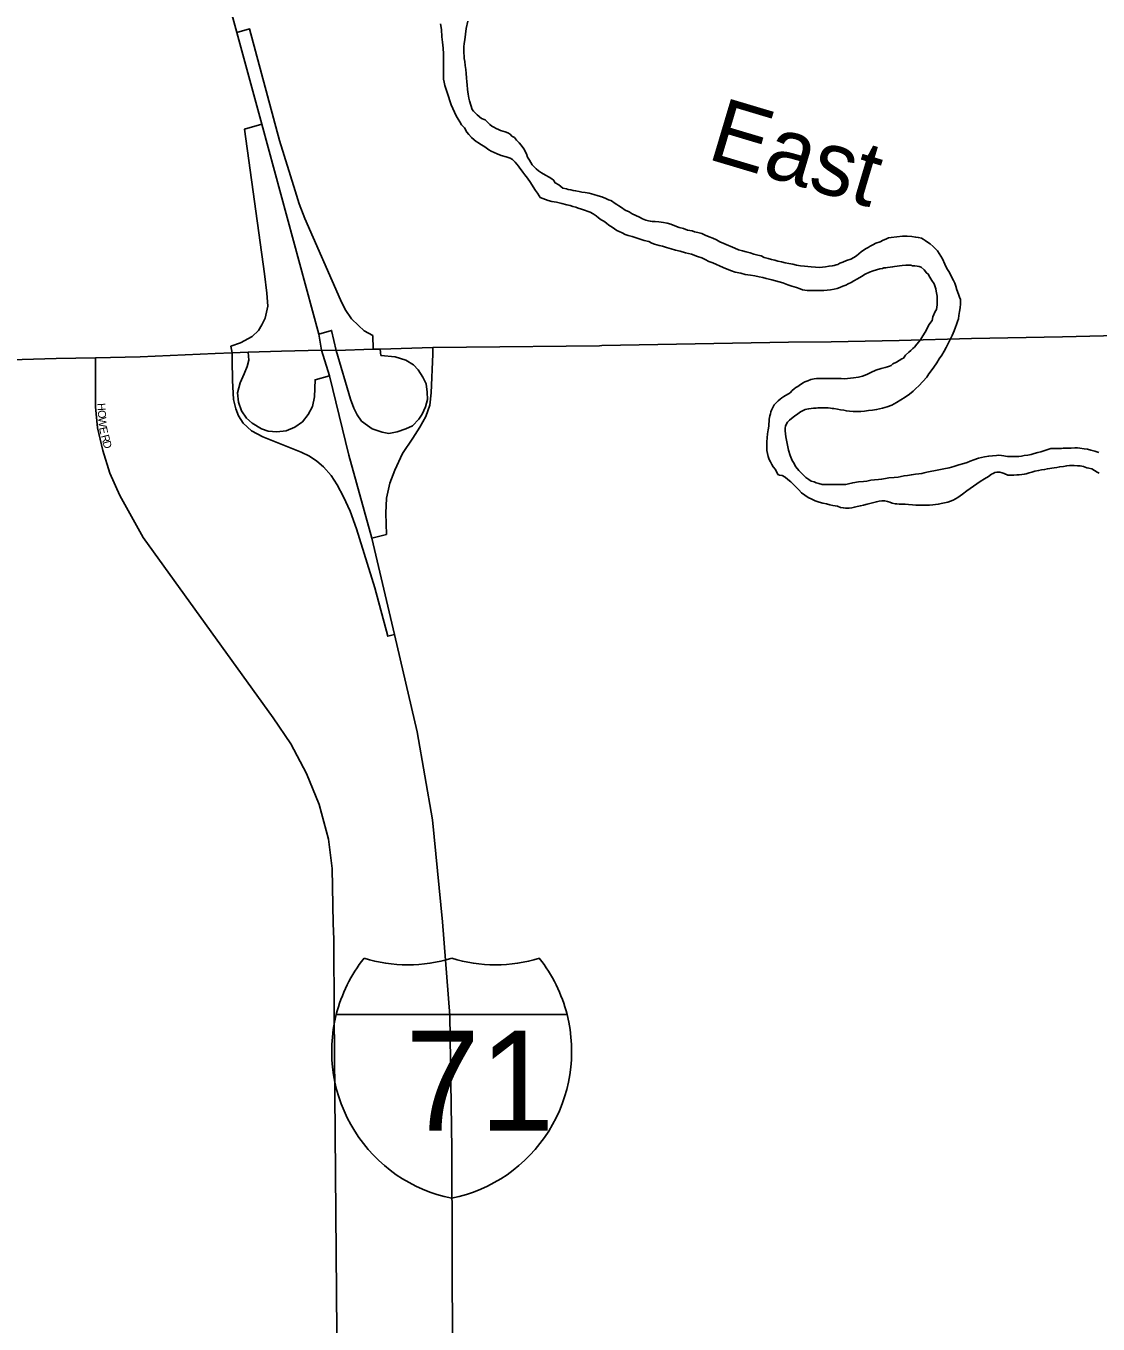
# Model space of a CAD drawing. Extents: x -561 to 1170, y 0 to 846.
# Drawn here: x 151.52 to 169.61, y 88.46 to 110.36 of the extents above; entities that cross this region are included whole.
import ezdxf

# ---------------------------------------------------------------- set-up
doc = ezdxf.new("R2010")
doc.units = 0
for name, color, linetype in [('GM_X_City_Street', 7, 'Continuous'), ('GM_X_City_Street_Text', 7, 'Continuous'), ('GM_X_Interchange_Ramps', 7, 'Continuous'), ('GM_X_Interstate_Location', 7, 'Continuous'), ('GM_X_Interstate_Route', 7, 'Continuous'), ('GM_X_Interstate_Shield', 7, 'Continuous'), ('GM_X_Major_River', 7, 'Continuous'), ('GM_X_Major_River_Text', 7, 'Continuous'), ('GM_X_State_Route', 7, 'Continuous')]:
    doc.layers.add(name, color=color, linetype=linetype)

msp = doc.modelspace()

# ---------------------------------------------------------------- linework, layer by layer
at = {"layer": 'GM_X_City_Street'}
for points in [[(156.71, 95.219), (156.688, 96.145), (156.628, 96.639), (156.469, 97.228), (156.258, 97.751), (155.993, 98.252), (155.695, 98.69), (153.504, 101.729), (153.108, 102.442), (152.94, 102.819), (152.819, 103.197), (152.731, 103.581), (152.697, 103.938), (152.697, 104.764)], [(156.783, 86.988), (156.727, 93.684), (156.717, 94.954), (156.71, 95.219)]]:
    msp.add_lwpolyline(points, dxfattribs=at)
at = {"layer": 'GM_X_Interchange_Ramps'}
for points in [[(157.384, 104.908), (157.378, 105.138), (157.232, 105.219), (157.134, 105.306), (157.015, 105.423), (156.912, 105.579), (156.833, 105.741), (156.232, 107.111), (156.134, 107.36), (156.067, 107.578), (155.803, 108.427), (155.296, 110.312), (155.084, 110.252)], [(155.505, 108.702), (155.21, 108.619), (155.55, 106.182), (155.59, 105.851), (155.604, 105.635), (155.563, 105.432), (155.502, 105.317), (155.445, 105.221), (155.34, 105.121), (155.144, 105.013), (154.982, 104.959), (155.002, 104.847)], [(157.503, 104.911), (157.513, 104.804), (157.754, 104.777), (157.934, 104.725), (158.061, 104.645), (158.14, 104.562), (158.223, 104.435), (158.275, 104.322), (158.295, 104.183), (158.297, 104.061), (158.265, 103.935), (158.207, 103.81), (158.151, 103.726), (158.047, 103.614), (157.932, 103.563), (157.79, 103.513), (157.645, 103.486), (157.533, 103.506), (157.367, 103.563), (157.286, 103.618), (157.188, 103.695), (157.114, 103.803), (157.057, 103.915), (156.999, 104.064), (156.756, 104.888), (156.681, 105.224), (156.466, 105.162)], [(157.361, 101.719), (157.605, 101.782), (157.598, 102.14), (157.608, 102.392), (157.662, 102.648), (157.747, 102.867), (157.878, 103.148), (158.052, 103.409), (158.17, 103.59), (158.27, 103.77), (158.341, 103.964), (158.364, 104.171), (158.392, 104.826), (158.387, 104.939)], [(155.002, 104.847), (155.002, 104.723), (155.01, 104.379), (155.027, 104.058), (155.065, 103.904), (155.11, 103.784), (155.187, 103.66), (155.329, 103.532), (155.521, 103.43), (156.17, 103.169), (156.309, 103.106), (156.433, 103.017), (156.542, 102.923), (156.672, 102.779), (156.773, 102.618), (156.884, 102.416), (156.993, 102.174), (157.1, 101.875), (157.411, 100.882), (157.63, 100.066), (157.741, 100.094)], [(156.647, 104.458), (156.402, 104.393), (156.392, 104.102), (156.361, 103.94), (156.288, 103.805), (156.193, 103.683), (156.062, 103.594), (155.915, 103.533), (155.757, 103.515), (155.61, 103.524), (155.501, 103.565), (155.342, 103.661), (155.246, 103.747), (155.161, 103.87), (155.11, 104.015), (155.096, 104.173), (155.136, 104.338), (155.207, 104.494), (155.256, 104.617), (155.287, 104.721), (155.275, 104.86)]]:
    msp.add_lwpolyline(points, dxfattribs=at)
at = {"layer": 'GM_X_Interstate_Route'}
for points in [[(156.513, 104.891), (156.466, 105.162), (155.505, 108.702), (155.084, 110.252), (153.768, 115.093), (153.127, 117.482), (152.86, 118.791), (152.62, 120.081), (152.498, 121.009), (152.35, 122.472), (152.22, 124.261)], [(159.707, 72.107), (159.003, 79.45), (158.736, 82.784), (158.71, 91.411), (158.678, 93.667), (158.555, 95.249), (158.385, 96.969), (158.124, 98.452), (157.741, 100.094), (157.361, 101.719), (156.974, 103.122), (156.647, 104.458), (156.513, 104.891)]]:
    msp.add_lwpolyline(points, dxfattribs=at)
at = {"layer": 'GM_X_Interstate_Shield'}
for p, q in [((156.76, 93.682), (160.655, 93.682)), ((160.655, 93.682), (156.76, 93.682)), ((160.655, 93.682), (156.76, 93.682))]:
    msp.add_line(p, q, dxfattribs=at)
for centre, start, end in [((159.214, 93.062), 141.669, 165.8066), ((157.968, 97.052), 253.0091, 286.9909), ((159.447, 97.052), 253.0091, 286.9909), ((158.201, 93.062), 14.1934, 38.331), ((159.214, 93.062), 165.8066, 258.463), ((158.201, 93.062), 281.537, 14.1934)]:
    msp.add_arc(centre, 2.531, start, end, dxfattribs=at)
at = {"layer": 'GM_X_Major_River'}
for points in [[(162.563, 106.562), (162.482, 106.577), (162.411, 106.603), (162.335, 106.624), (162.264, 106.645), (162.21, 106.655), (162.172, 106.671), (162.129, 106.681), (162.085, 106.697), (162.036, 106.723), (161.955, 106.744), (161.889, 106.765), (161.819, 106.786), (161.754, 106.807), (161.688, 106.827), (161.634, 106.843), (161.585, 106.87), (161.531, 106.891), (161.493, 106.912), (161.454, 106.938), (161.416, 106.965), (161.362, 107.002), (161.318, 107.034), (161.274, 107.066), (161.231, 107.093), (161.187, 107.125), (161.143, 107.157), (161.094, 107.189), (161.045, 107.22), (160.996, 107.236), (160.964, 107.247), (160.931, 107.257), (160.898, 107.273), (160.844, 107.288), (160.8, 107.304), (160.752, 107.314), (160.708, 107.33), (160.648, 107.346), (160.567, 107.366), (160.475, 107.387), (160.399, 107.402), (160.334, 107.418), (160.29, 107.433), (160.203, 107.47), (160.181, 107.497), (160.154, 107.54), (160.121, 107.588), (160.082, 107.647), (160.038, 107.723), (159.988, 107.793), (159.944, 107.852), (159.906, 107.894), (159.878, 107.932), (159.856, 107.964), (159.834, 107.996), (159.806, 108.029), (159.779, 108.066), (159.735, 108.109), (159.692, 108.13), (159.626, 108.151), (159.545, 108.177), (159.474, 108.203), (159.425, 108.224), (159.371, 108.251), (159.333, 108.272), (159.289, 108.304), (159.251, 108.331), (159.202, 108.362), (159.158, 108.389), (159.12, 108.41), (159.087, 108.442), (159.043, 108.48), (158.999, 108.528), (158.961, 108.571), (158.922, 108.641), (158.873, 108.694), (158.845, 108.743), (158.817, 108.791), (158.784, 108.845), (158.756, 108.909), (158.728, 108.969), (158.701, 109.028), (158.678, 109.098), (158.655, 109.174), (158.633, 109.238), (158.616, 109.292), (158.594, 109.357), (158.582, 109.411), (158.571, 109.465), (158.57, 109.53), (158.569, 109.606), (158.57, 109.893), (158.564, 109.985), (158.552, 110.088), (158.54, 110.18), (158.533, 110.299), (158.52, 110.396)], [(158.98, 110.44), (158.954, 110.32), (158.939, 110.223), (158.93, 110.13), (158.92, 110.065), (158.915, 110.011), (158.91, 109.978), (158.91, 109.941), (158.911, 109.897), (158.917, 109.865), (158.918, 109.811), (158.929, 109.762), (158.935, 109.697), (158.947, 109.627), (158.953, 109.562), (158.96, 109.486), (158.961, 109.421), (158.967, 109.367), (158.973, 109.291), (158.985, 109.21), (158.997, 109.145), (159.008, 109.097), (159.053, 108.951), (159.075, 108.924), (159.136, 108.86), (159.212, 108.801), (159.272, 108.775), (159.321, 108.727), (159.354, 108.7), (159.387, 108.673), (159.42, 108.652), (159.458, 108.631), (159.496, 108.615), (159.534, 108.599), (159.572, 108.589), (159.61, 108.573), (159.654, 108.558), (159.692, 108.536), (159.725, 108.504), (159.768, 108.478), (159.801, 108.435), (159.845, 108.392), (159.878, 108.349), (159.906, 108.311), (159.928, 108.285), (159.944, 108.252), (159.972, 108.204), (159.989, 108.15), (160.022, 108.096), (160.044, 108.059), (160.066, 108.021), (160.094, 107.989), (160.132, 107.951), (160.17, 107.919), (160.225, 107.882), (160.29, 107.845), (160.35, 107.808), (160.399, 107.781), (160.427, 107.76), (160.454, 107.712), (160.514, 107.68), (160.547, 107.653), (160.585, 107.626), (160.645, 107.611), (160.672, 107.6), (160.716, 107.596), (160.759, 107.585), (160.797, 107.58), (160.857, 107.57), (160.905, 107.56), (160.96, 107.55), (161.025, 107.54), (161.106, 107.519), (161.182, 107.498), (161.242, 107.477), (161.307, 107.451), (161.356, 107.43), (161.394, 107.414), (161.421, 107.398), (161.449, 107.377), (161.492, 107.35), (161.53, 107.329), (161.574, 107.297), (161.634, 107.255)], [(161.634, 107.255), (161.7, 107.223), (161.754, 107.191), (161.814, 107.165), (161.874, 107.133), (161.928, 107.107), (161.983, 107.086), (162.026, 107.075), (162.059, 107.07), (162.091, 107.06), (162.14, 107.061), (162.205, 107.056), (162.281, 107.046), (162.346, 107.036), (162.405, 107.015), (162.471, 106.989), (162.547, 106.963), (162.617, 106.942), (162.688, 106.916), (162.764, 106.906), (162.807, 106.89), (162.862, 106.874), (162.927, 106.859), (162.987, 106.833), (163.052, 106.806), (163.117, 106.78), (163.177, 106.754), (163.232, 106.722), (163.297, 106.69), (163.487, 106.611), (163.547, 106.585), (163.612, 106.569), (163.677, 106.549), (163.742, 106.533), (163.808, 106.512), (163.873, 106.497), (163.927, 106.481), (163.981, 106.455), (164.047, 106.439), (164.106, 106.424), (164.161, 106.408), (164.21, 106.393), (164.275, 106.382), (164.334, 106.367), (164.399, 106.352), (164.464, 106.341), (164.524, 106.326), (164.595, 106.316), (164.66, 106.311), (164.719, 106.301), (164.773, 106.297), (164.849, 106.292), (164.909, 106.287), (164.963, 106.293), (165.017, 106.299), (165.076, 106.311), (165.13, 106.312), (165.163, 106.318), (165.195, 106.329), (165.222, 106.335), (165.259, 106.357), (165.308, 106.379), (165.372, 106.407), (165.442, 106.429), (165.496, 106.457), (165.539, 106.485), (165.576, 106.518), (165.619, 106.551), (165.657, 106.578), (165.7, 106.606), (165.737, 106.622), (165.77, 106.645), (165.812, 106.667), (165.866, 106.694), (165.936, 106.722), (165.99, 106.745), (166.033, 106.767), (166.076, 106.784), (166.125, 106.795), (166.314, 106.814), (166.395, 106.815), (166.471, 106.81), (166.536, 106.8), (166.584, 106.79), (166.633, 106.78), (166.666, 106.764), (166.699, 106.743), (166.737, 106.716), (166.781, 106.684), (166.83, 106.641), (166.874, 106.604), (166.907, 106.566), (166.934, 106.523), (166.962, 106.48), (166.989, 106.432), (167.028, 106.34), (167.062, 106.27), (167.095, 106.217), (167.123, 106.168), (167.145, 106.12), (167.173, 106.066)], [(166.126, 104.634), (166.153, 104.661), (166.212, 104.689), (166.26, 104.717), (166.303, 104.744), (166.33, 104.756), (166.367, 104.805), (166.42, 104.86), (166.458, 104.887), (166.49, 104.92), (166.517, 104.942), (166.559, 104.991), (166.591, 105.03), (166.618, 105.068), (166.639, 105.106), (166.713, 105.226), (166.734, 105.275), (166.766, 105.324), (166.792, 105.362), (166.814, 105.39), (166.829, 105.455), (166.866, 105.542), (166.887, 105.575), (166.892, 105.618), (166.902, 105.656), (166.9, 105.803), (166.883, 105.889), (166.877, 105.927), (166.849, 106.013), (166.81, 106.067), (166.777, 106.121), (166.749, 106.174), (166.717, 106.196), (166.683, 106.249), (166.629, 106.292), (166.596, 106.303), (166.564, 106.308), (166.52, 106.313), (166.482, 106.317), (166.455, 106.323), (166.417, 106.327), (166.369, 106.327), (166.309, 106.321), (166.18, 106.303), (166.147, 106.297), (166.104, 106.291), (166.061, 106.285), (166.029, 106.279), (166.001, 106.279), (165.975, 106.268), (165.931, 106.262), (165.878, 106.245), (165.818, 106.228), (165.759, 106.206), (165.684, 106.172), (165.625, 106.134), (165.555, 106.095), (165.496, 106.062), (165.448, 106.034), (165.399, 106.012), (165.356, 105.989), (165.308, 105.973), (165.259, 105.95), (165.211, 105.934), (165.162, 105.922), (165.098, 105.911), (164.99, 105.898), (164.908, 105.897), (164.827, 105.896), (164.762, 105.896), (164.708, 105.9), (164.665, 105.905), (164.627, 105.91), (164.589, 105.926), (164.524, 105.947), (164.448, 105.973), (164.377, 105.994), (164.295, 106.025), (164.236, 106.046), (164.171, 106.062), (164.111, 106.077), (164.062, 106.087), (164.013, 106.103), (163.959, 106.119), (163.894, 106.129), (163.823, 106.144), (163.747, 106.159), (163.661, 106.169), (163.585, 106.19), (163.492, 106.21), (163.427, 106.231), (163.357, 106.258), (163.291, 106.284), (163.112, 106.363), (163.047, 106.389), (162.987, 106.421), (162.927, 106.447), (162.856, 106.473), (162.753, 106.51), (162.655, 106.536), (162.563, 106.562)], [(167.173, 106.066), (167.195, 106.023), (167.212, 105.974), (167.234, 105.91), (167.257, 105.839), (167.279, 105.786), (167.291, 105.748), (167.291, 105.715), (167.291, 105.672), (167.287, 105.607), (167.277, 105.542), (167.267, 105.477), (167.257, 105.422), (167.241, 105.373), (167.226, 105.324), (167.21, 105.281), (167.184, 105.216), (167.152, 105.139), (167.11, 105.047), (167.079, 104.992), (167.052, 104.938), (167.015, 104.872), (166.978, 104.807), (166.936, 104.747), (166.893, 104.676), (166.846, 104.605), (166.798, 104.545), (166.761, 104.49), (166.723, 104.435), (166.59, 104.288), (166.542, 104.244), (166.494, 104.2), (166.435, 104.15), (166.36, 104.101), (166.285, 104.051), (166.215, 104.007), (166.135, 103.962), (166.054, 103.934), (165.978, 103.912), (165.876, 103.889), (165.806, 103.877), (165.741, 103.871), (165.676, 103.865), (165.611, 103.858), (165.541, 103.858), (165.482, 103.857), (165.422, 103.862), (165.368, 103.866), (165.324, 103.877), (165.27, 103.887), (165.216, 103.897), (165.156, 103.907), (165.129, 103.907), (165.102, 103.912), (165.059, 103.917), (165.01, 103.916), (164.961, 103.916), (164.924, 103.92), (164.886, 103.92), (164.859, 103.914), (164.815, 103.914), (164.772, 103.908), (164.734, 103.902), (164.702, 103.896), (164.67, 103.89), (164.637, 103.874), (164.594, 103.851), (164.546, 103.818), (164.493, 103.78), (164.444, 103.741), (164.407, 103.708), (164.375, 103.675), (164.354, 103.637), (164.338, 103.61), (164.333, 103.577), (164.334, 103.529), (164.34, 103.48), (164.346, 103.431), (164.392, 103.204), (164.42, 103.113), (164.454, 103.032), (164.476, 102.994), (164.515, 102.924), (164.564, 102.86), (164.613, 102.817), (164.646, 102.785), (164.685, 102.742), (164.734, 102.71), (164.772, 102.684), (164.826, 102.668), (164.859, 102.652), (164.902, 102.642), (164.957, 102.626), (165.027, 102.627), (165.108, 102.628), (165.179, 102.624), (165.227, 102.624), (165.26, 102.625), (165.292, 102.625), (165.319, 102.625), (165.357, 102.626)], [(166.362, 102.291), (166.313, 102.296), (166.259, 102.296), (166.221, 102.301), (166.189, 102.3), (166.14, 102.31), (166.102, 102.326), (166.064, 102.337), (166.015, 102.347), (165.966, 102.352), (165.923, 102.346), (165.875, 102.334), (165.81, 102.317), (165.718, 102.294), (165.659, 102.277), (165.605, 102.266), (165.551, 102.254), (165.503, 102.243), (165.46, 102.232), (165.416, 102.226), (165.378, 102.225), (165.351, 102.225), (165.319, 102.23), (165.27, 102.24), (165.216, 102.261), (165.14, 102.271), (165.086, 102.281), (165.031, 102.297), (164.972, 102.312), (164.907, 102.328), (164.841, 102.349), (164.782, 102.375), (164.722, 102.407), (164.612, 102.487), (164.563, 102.535), (164.525, 102.572), (164.481, 102.62), (164.431, 102.669), (164.382, 102.711), (164.333, 102.749), (164.284, 102.775), (164.241, 102.785), (164.213, 102.796), (164.174, 102.877), (164.131, 102.925), (164.108, 102.963), (164.086, 103.006), (164.064, 103.049), (164.047, 103.097), (164.036, 103.151), (164.024, 103.2), (164.023, 103.27), (164.028, 103.346), (164.032, 103.411), (164.037, 103.482), (164.047, 103.547), (164.057, 103.612), (164.066, 103.726), (164.076, 103.785), (164.086, 103.818), (164.091, 103.851), (164.102, 103.878), (164.128, 103.927), (164.149, 103.971), (164.181, 104.003), (164.219, 104.036), (164.251, 104.064), (164.278, 104.086), (164.31, 104.108), (164.417, 104.169), (164.454, 104.213), (164.487, 104.24), (164.513, 104.262), (164.546, 104.279), (164.572, 104.295), (164.626, 104.334), (164.669, 104.356), (164.717, 104.373), (164.766, 104.395), (164.825, 104.407), (164.863, 104.413), (164.906, 104.413), (164.966, 104.414), (165.02, 104.415), (165.085, 104.415), (165.155, 104.416), (165.225, 104.412), (165.279, 104.412), (165.328, 104.407), (165.388, 104.414), (165.49, 104.426), (165.571, 104.438), (165.641, 104.455), (165.711, 104.483), (165.781, 104.516), (165.867, 104.555), (165.953, 104.583), (166.024, 104.6), (166.061, 104.611), (166.094, 104.623), (166.126, 104.634)], [(165.357, 102.626), (165.406, 102.637), (165.476, 102.654), (165.573, 102.672), (165.654, 102.678), (165.713, 102.684), (165.778, 102.696), (165.843, 102.702), (165.908, 102.708), (165.962, 102.714), (166.026, 102.726), (166.086, 102.738), (166.172, 102.744), (166.243, 102.75), (166.291, 102.762), (166.34, 102.773), (166.399, 102.779), (166.464, 102.791), (166.534, 102.797), (166.593, 102.803), (166.642, 102.809), (166.68, 102.821), (166.728, 102.832), (166.928, 102.873), (167.014, 102.89), (167.101, 102.907), (167.181, 102.93), (167.268, 102.958), (167.348, 102.981), (167.408, 102.998), (167.456, 103.02), (167.521, 103.042), (167.596, 103.07), (167.699, 103.093), (167.769, 103.105), (167.834, 103.111), (167.898, 103.117), (167.942, 103.118), (167.985, 103.113), (168.023, 103.108), (168.055, 103.103), (168.088, 103.098), (168.12, 103.098), (168.169, 103.099), (168.239, 103.1), (168.277, 103.1), (168.321, 103.101), (168.369, 103.112), (168.429, 103.118), (168.488, 103.13), (168.536, 103.147), (168.596, 103.164), (168.65, 103.175), (168.698, 103.192), (168.752, 103.209), (168.816, 103.231), (168.892, 103.232), (168.925, 103.233), (168.957, 103.233), (168.995, 103.234), (169.027, 103.239), (169.071, 103.24), (169.114, 103.241), (169.163, 103.236), (169.222, 103.242), (169.265, 103.242), (169.309, 103.238), (169.379, 103.228), (169.439, 103.223), (169.493, 103.207), (169.558, 103.186), (169.629, 103.166)], [(169.633, 102.814), (169.601, 102.835), (169.557, 102.861), (169.508, 102.888), (169.459, 102.898), (169.427, 102.909), (169.399, 102.919), (169.367, 102.93), (169.34, 102.935), (169.313, 102.94), (169.269, 102.939), (169.21, 102.944), (169.134, 102.943), (169.085, 102.942), (169.031, 102.931), (168.967, 102.925), (168.918, 102.913), (168.875, 102.907), (168.837, 102.901), (168.799, 102.895), (168.761, 102.89), (168.713, 102.878), (168.659, 102.872), (168.61, 102.861), (168.546, 102.849), (168.497, 102.832), (168.454, 102.821), (168.4, 102.804), (168.368, 102.798), (168.33, 102.792), (168.281, 102.786), (168.244, 102.786), (168.195, 102.78), (168.125, 102.784), (168.092, 102.784), (168.032, 102.81), (167.994, 102.821), (167.956, 102.831), (167.907, 102.836), (167.87, 102.825), (167.843, 102.813), (167.816, 102.802), (167.768, 102.758), (167.698, 102.719), (167.628, 102.675), (167.403, 102.521), (167.328, 102.46), (167.248, 102.405), (167.167, 102.361), (167.081, 102.327), (166.995, 102.31), (166.919, 102.293), (166.828, 102.281), (166.773, 102.275), (166.719, 102.274), (166.66, 102.279), (166.6, 102.278), (166.541, 102.277), (166.481, 102.282), (166.416, 102.287), (166.362, 102.291)]]:
    msp.add_lwpolyline(points, dxfattribs=at)
at = {"layer": 'GM_X_State_Route'}
for points in [[(161.243, 104.968), (164.39, 105.027), (165.11, 105.033), (166.261, 105.056), (167.48, 105.087), (169.012, 105.119), (170.635, 105.158), (171.512, 105.176), (172.144, 105.192), (173.637, 105.223), (173.809, 105.228)], [(144.932, 104.976), (145.398, 104.846), (145.878, 104.711), (146.189, 104.653), (146.581, 104.607), (146.801, 104.6), (147.805, 104.628), (150.118, 104.695), (152.034, 104.753), (152.697, 104.764), (153.449, 104.781), (154.717, 104.835)], [(155.837, 104.874), (156.513, 104.891), (156.756, 104.888), (157.384, 104.908), (157.503, 104.911), (158.387, 104.939), (158.958, 104.944)], [(158.958, 104.944), (161.203, 104.967), (161.243, 104.968)], [(154.717, 104.835), (155.002, 104.847), (155.275, 104.86), (155.837, 104.874)]]:
    msp.add_lwpolyline(points, dxfattribs=at)

# ---------------------------------------------------------------- texts
at = {"layer": 'GM_X_City_Street_Text'}
for s, rotation, p in [('H', 273.3896, (152.728, 103.995)), ('O', 273.3678, (152.735, 103.876)), ('W', 274.193, (152.742, 103.756)), ('E', 282.4411, (152.756, 103.581)), ('R', 284.9264, (152.788, 103.447)), ('D', 284.9427, (152.815, 103.344))]:
    msp.add_text(s, height=0.135, rotation=rotation, dxfattribs=at).set_placement(p)
at = {"layer": 'GM_X_Interstate_Location'}
for s in ['.', '-', ',']:
    msp.add_text(s, height=0.0027, dxfattribs=at).set_placement((158.707, 92.605))
msp.add_text('71', height=0.0027, rotation=0, dxfattribs=at).set_placement((158.156, 92.046))
at = {"layer": 'GM_X_Interstate_Shield'}
msp.add_text('71', height=1.6875, dxfattribs=at).set_placement((157.928, 91.721))
at = {"layer": 'GM_X_Major_River_Text'}
msp.add_text('East', height=1.0806, rotation=343.3783, dxfattribs=at).set_placement((162.996, 108.127))

doc.saveas('drawing.dxf')
